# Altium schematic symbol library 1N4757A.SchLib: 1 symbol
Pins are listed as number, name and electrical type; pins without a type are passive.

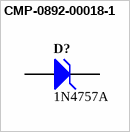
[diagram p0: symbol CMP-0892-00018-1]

## CMP-0892-00018-1
designator D?, comment 1N4757A
Zener Diode, 51V, 1W, 5%, -65 to 200 degC, 2-Pin DO-41, Body 2.72 x 5.2 mm, RoHS; Manufacturer: Fairchild Semiconductor; Test Current IZ (mA): 5; ZZ (Max) (ohm): 95; VZ (Min.) (V): 48.45; VZ (Max.) (V): 53.55; PD (W): 1
footprint FAIR-DO-41-2_V (2-Leads, Axial leaded, Body 2.72x5.2mm, Pin Spacing 9mm)
pins: 1 A, 2 K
